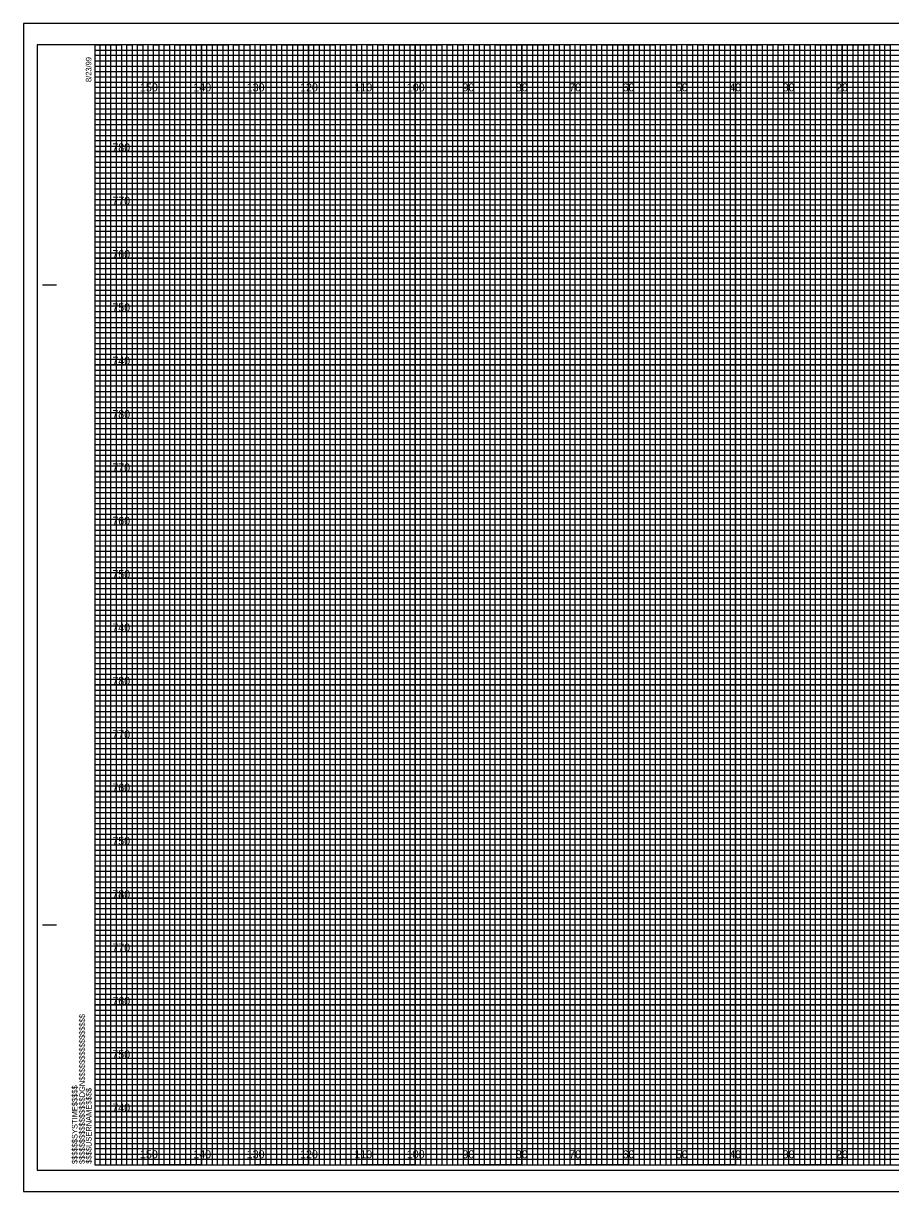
# Model space of a CAD drawing. Extents: x -13 to 323, y 215 to 434.
# Drawn here: x -13.4 to 149.1, y 215 to 434 of the extents above; entities that cross this region are included whole.
import ezdxf

# ---------------------------------------------------------------- set-up
doc = ezdxf.new("R2010")
doc.units = 0
for name, color, linetype in [('Prop XS Elevation Labels', 7, 'Continuous'), ('Prop XS Offset Labels', 7, 'Continuous'), ('Sheet Cross Section CELL', 7, 'Continuous'), ('Sheet Cross Section Grid Major CELL', 7, 'Continuous'), ('Sheet Cross Section Grid Middle CELL', 7, 'Continuous'), ('Sheet Cross Section Grid Minor 1 CELL', 7, 'Continuous'), ('Sheet Cross Section Grid Minor 2 CELL', 7, 'Continuous'), ('Sheet Cutting Line CELL', 7, 'Continuous'), ('Sheet DOT Grid CELL', 7, 'Continuous'), ('Sheet Plot Border Inside CELL', 7, 'Continuous'), ('Sheet Plot Border Outside CELL', 7, 'Continuous')]:
    doc.layers.add(name, color=color, linetype=linetype)

msp = doc.modelspace()

# ---------------------------------------------------------------- linework, layer by layer
at = {"layer": 'Sheet Cross Section CELL'}
for p, q in [((-9.8, 385), (-7.3, 385)), ((-9.7, 385), (-7.2, 385)), ((-9.8, 265), (-7.3, 265)), ((-9.7, 265), (-7.2, 265)), ((0, 220), (0, 220)), ((0, 220), (0, 220)), ((0, 220), (0, 220)), ((0, 220), (0, 220)), ((0, 220), (0, 220)), ((0, 220), (0, 220)), ((0, 220), (0, 220))]:
    msp.add_line(p, q, dxfattribs=at)
msp.add_lwpolyline([(320, 430), (0, 430), (0, 220), (320, 220)], close=True, dxfattribs=at)
at = {"layer": 'Sheet Cross Section Grid Major CELL'}
for p, q in [((10, 430), (0, 430)), ((10, 220), (10, 430)), ((30, 430), (20, 430)), ((20, 430), (20, 220)), ((30, 220), (30, 430)), ((50, 430), (40, 430)), ((40, 430), (40, 220)), ((50, 220), (50, 430)), ((70, 430), (60, 430)), ((60, 430), (60, 220)), ((70, 220), (70, 430)), ((90, 430), (80, 430)), ((80, 430), (80, 220)), ((90, 220), (90, 430)), ((110, 430), (100, 430)), ((100, 430), (100, 220)), ((110, 220), (110, 430)), ((130, 430), (120, 430)), ((120, 430), (120, 220)), ((130, 220), (130, 430)), ((150, 430), (140, 430)), ((140, 430), (140, 220)), ((20, 220), (10, 220)), ((40, 220), (30, 220)), ((60, 220), (50, 220)), ((80, 220), (70, 220)), ((100, 220), (90, 220)), ((120, 220), (110, 220)), ((140, 220), (130, 220))]:
    msp.add_line(p, q, dxfattribs=at)
for points in [[(0, 420), (320, 420), (320, 410), (0, 410)], [(0, 400), (320, 400), (320, 390), (0, 390)], [(0, 380), (320, 380), (320, 370), (0, 370)], [(0, 360), (320, 360), (320, 350), (0, 350)], [(0, 340), (320, 340), (320, 330), (0, 330)], [(0, 320), (320, 320), (320, 310), (0, 310)], [(0, 300), (320, 300), (320, 290), (0, 290)], [(0, 280), (320, 280), (320, 270), (0, 270)], [(0, 260), (320, 260), (320, 250), (0, 250)], [(0, 240), (320, 240), (320, 230), (0, 230)]]:
    msp.add_lwpolyline(points, dxfattribs=at)
at = {"layer": 'Sheet Cross Section Grid Middle CELL'}
for points in [[(0, 430), (5, 430), (5, 220), (15, 220), (15, 430), (25, 430), (25, 220), (35, 220), (35, 430), (45, 430), (45, 220), (55, 220), (55, 430), (65, 430), (65, 220), (75, 220), (75, 430), (85, 430), (85, 220), (95, 220), (95, 430), (105, 430), (105, 220), (115, 220), (115, 430), (125, 430), (125, 220), (135, 220), (135, 430), (145, 430), (145, 220), (155, 220)], [(0, 425), (275, 425)], [(0, 405), (320, 405), (320, 415), (0, 415)], [(0, 385), (320, 385), (320, 395), (0, 395)], [(0, 365), (320, 365), (320, 375), (0, 375)], [(0, 345), (320, 345), (320, 355), (0, 355)], [(0, 325), (320, 325), (320, 335), (0, 335)], [(0, 305), (320, 305), (320, 315), (0, 315)], [(0, 285), (320, 285), (320, 295), (0, 295)], [(0, 265), (320, 265), (320, 275), (0, 275)], [(0, 245), (320, 245), (320, 255), (0, 255)], [(0, 225), (320, 225), (320, 235), (0, 235)]]:
    msp.add_lwpolyline(points, dxfattribs=at)
at = {"layer": 'Sheet Cross Section Grid Minor 1 CELL'}
for p, q in [((0, 429), (260, 429)), ((260, 427.98), (0, 427.98)), ((0, 427.98), (0, 427)), ((0, 427), (260, 427)), ((260, 425.89), (0, 425.89)), ((0, 425.89), (0, 424)), ((0, 424), (320, 424))]:
    msp.add_line(p, q, dxfattribs=at)
for points in [[(0, 423), (270, 423), (320, 423), (320, 422), (0, 422)], [(0, 421), (320, 421), (320, 419), (0, 419)], [(0, 418), (320, 418), (320, 417), (0, 416.98)], [(0, 416), (320, 416), (320, 414), (0, 414)], [(0, 413), (320, 413), (320, 412), (0, 412)], [(0, 411), (320, 411), (320, 409), (0, 409)], [(0, 408), (320, 408), (320, 407), (0, 407)], [(0, 406), (320, 406), (320, 404), (0, 404)], [(0, 403), (320, 403), (320, 402), (0, 402)], [(0, 401), (320, 401), (320, 399), (0, 399)], [(0, 398), (320, 398), (320, 397), (0, 397)], [(0, 396), (320, 396), (320, 393.95), (320, 393), (320, 392), (0, 392)], [(0, 394), (320, 394), (320, 393), (0, 393)], [(0, 391), (320, 391), (320, 389), (0, 389.03)], [(0, 389.03), (320, 389), (320, 388), (0, 388)], [(0, 387), (320, 387), (320, 386), (0, 386)], [(0, 384), (320, 384), (320, 383), (0, 383)], [(0, 382), (320, 382), (320, 381), (0, 381)], [(-0.07, 378.89), (320, 378.89), (320, 377.88), (-0.07, 377.88)], [(0, 377), (320, 377), (320, 376), (0, 376)], [(0, 374), (320, 374), (320, 373), (0, 373)], [(0, 372), (320, 372), (320, 371), (0, 371)], [(0, 369), (320, 369), (320, 368), (0, 368)], [(0, 367), (320, 367), (320, 366), (0, 366)], [(0, 364), (320, 364), (320, 363), (0, 363)], [(0, 362), (320, 362), (320, 361), (0, 361)], [(0, 359), (320, 359), (319.99, 357.98), (0, 358)], [(0, 357), (320, 357), (320, 356), (0, 356)], [(0, 354), (320, 354), (320, 353), (0, 353)], [(0, 352), (320, 352), (320, 351), (0, 351)], [(0, 349), (320, 349), (320, 348), (0, 348)], [(0, 347), (320, 347), (320, 346), (0, 346)], [(0, 344), (320, 344), (320, 343), (0, 343)], [(0, 342), (320, 342), (320, 341), (0, 341)], [(0, 339), (320, 339), (320, 338), (0, 338)], [(0, 336.99), (320.07, 336.91), (320, 336), (0, 336)], [(0, 334), (320, 334), (320, 333), (0, 333)], [(0, 332), (320, 332), (320, 331), (0, 331)], [(0, 329), (320, 329), (320, 328), (0, 328)], [(0, 327), (320, 327), (320, 326), (0, 326)], [(0, 324), (320, 324), (320, 323), (0, 323)], [(0, 322), (320, 322), (320, 321), (0, 321)], [(0, 319), (320, 319), (320, 318), (0, 318)], [(0, 317), (320, 317), (320, 316), (0, 316)], [(0, 314), (320, 314), (320, 313), (0, 313)], [(0, 312), (320, 312), (320, 311), (0, 311)], [(0, 309), (320, 309), (320, 308), (0, 308)], [(0, 307), (320, 307), (320, 306), (0, 306)], [(0, 304), (320, 304), (320, 303), (0, 303)], [(0, 302), (320, 302), (320, 301), (0, 301)], [(0, 299), (320, 299), (319.99, 297.98), (0, 298)], [(0, 297), (320, 297), (320, 296), (0, 296)], [(0, 294), (320, 294), (320, 293), (0, 293)], [(0, 292), (320, 292), (320, 291), (0, 291)], [(0, 289), (320, 289), (320, 288), (0, 288)], [(0, 287), (320, 287), (320, 286), (0, 286)], [(0, 284), (320, 284), (320, 283), (0, 283)], [(0, 282), (320, 282), (320, 281), (0, 281)], [(0, 279), (320, 279), (320, 278), (0, 278)], [(0, 276.99), (320.07, 276.91), (320, 276), (0, 276)], [(0, 274), (320, 274), (320, 273), (0, 273)], [(0, 272), (320, 272), (320, 271), (0, 271)], [(0, 269), (320, 269), (320, 268), (0, 268)], [(0, 267), (320, 267), (320, 266), (0, 266)], [(0, 264), (320, 264), (320, 263), (0, 263)], [(0, 262), (320, 262), (320, 261), (0, 261)], [(0, 259), (320, 259), (320, 258), (0, 258)], [(0, 257), (320, 257), (320, 256), (0, 256)], [(0, 254), (320, 254), (320, 253), (0, 253)], [(0, 252), (320, 252), (320, 251), (0, 251)], [(0, 249), (320, 249), (320, 248), (0, 248)], [(0, 247), (320, 247), (320, 246), (0, 246)], [(0, 244), (320, 244), (320, 243), (0, 243)], [(0, 242), (320, 242), (320, 241), (0, 241)], [(0, 239), (320, 239), (320, 238), (0, 238)], [(0, 237), (320, 237), (320, 236), (0, 236)], [(0, 234), (320, 234), (320, 233), (0, 233)], [(0, 232), (320, 232), (320, 231), (0, 231)], [(0, 229), (320, 229), (320, 228), (0, 228)], [(0, 227), (320, 227), (320, 226), (0, 226)], [(0, 224), (320, 224), (320, 223), (0, 223)], [(0, 222), (320, 222), (320, 221), (0, 221)]]:
    msp.add_lwpolyline(points, dxfattribs=at)
at = {"layer": 'Sheet Cross Section Grid Minor 2 CELL'}
for points in [[(0, 220), (1, 220), (1, 430), (2, 430), (2, 220)], [(2, 220), (3, 220), (3, 430), (4, 430), (4, 220)], [(5, 220), (6, 220), (6, 430), (7, 430), (7, 220)], [(7, 220), (8, 220), (8, 430), (9, 430), (9, 220)], [(10, 220), (11, 220), (11, 430), (12, 430), (12, 220)], [(12, 220), (13, 220), (13, 430), (14, 430), (14, 220)], [(15, 220), (16, 220), (16, 430), (17, 430), (17, 220)], [(17, 220), (18, 220), (18, 430), (19, 430), (19, 220)], [(20, 220), (21, 220), (21, 430), (22, 430), (22, 220)], [(22, 220), (23, 220), (23, 430), (24, 430), (24, 220)], [(25, 220), (26, 220), (26, 430), (27, 430), (27, 220)], [(27, 220), (28, 220), (28, 430), (29, 430), (29, 220)], [(30, 220), (31, 220), (31, 430), (32, 430), (32, 220)], [(32, 220), (33, 220), (33, 430), (34, 430), (34, 220)], [(35, 220), (36, 220), (36, 430), (37, 430), (37, 220)], [(37, 220), (38, 220), (38, 430), (39, 430), (39, 220)], [(40, 220), (41, 220), (41, 430), (42, 430), (42, 220)], [(42, 220), (43, 220), (43, 430), (44, 430), (44, 220)], [(45, 220), (46, 220), (46, 430), (47, 430), (47, 220)], [(47, 220), (48, 220), (48, 430), (49, 430), (49, 220)], [(50, 220), (51, 220), (51, 430), (52, 430), (52, 220)], [(52, 220), (53, 220), (53, 430), (54, 430), (54, 220)], [(55, 220), (56, 220), (56, 430), (57, 430), (57, 220)], [(57, 220), (58, 220), (58, 430), (59, 430), (59, 220)], [(60, 220), (61, 220), (61, 430), (62, 430), (62, 220)], [(62, 220), (63, 220), (63, 430), (64, 430), (64, 220)], [(65, 220), (66, 220), (66, 430), (67, 430), (67, 220)], [(67, 220), (68, 220), (68, 430), (69, 430), (69, 220)], [(70, 220), (71, 220), (71, 430), (72, 430), (72, 220)], [(72, 220), (73, 220), (73, 430), (74, 430), (74, 220)], [(75, 220), (76, 220), (76, 430), (77, 430), (77, 220)], [(77, 220), (78, 220), (78, 430), (79, 430), (79, 220)], [(80, 220), (81, 220), (81, 430), (82, 430), (82, 220)], [(82, 220), (83, 220), (83, 430), (84, 430), (84, 220)], [(85, 220), (86, 220), (86, 430), (87, 430), (87, 220)], [(87, 220), (88, 220), (88, 430), (89, 430), (89, 220)], [(90, 220), (91, 220), (91, 430), (92, 430), (92, 220)], [(92, 220), (93, 220), (93, 430), (94, 430), (94, 220)], [(95, 220), (96, 220), (96, 430), (97, 430), (97, 220)], [(97, 220), (98, 220), (98, 430), (99, 430), (99, 220)], [(100, 220), (101, 220), (101, 430), (102, 430), (102, 220)], [(102, 220), (103, 220), (103, 430), (104, 430), (104, 220)], [(105, 220), (106, 220), (106, 430), (107, 430), (107, 220)], [(107, 220), (108, 220), (108, 430), (109, 430), (109, 220)], [(110, 220), (111, 220), (111, 430), (112, 430), (112, 220)], [(112, 220), (113, 220), (113, 430), (114, 430), (114, 220)], [(115, 220), (116, 220), (116, 430), (117, 430), (117, 220)], [(117, 220), (118, 220), (118, 430), (119, 430), (119, 220)], [(120, 220), (121, 220), (121, 430), (122, 430), (122, 220)], [(122, 220), (123, 220), (123, 430), (124, 430), (124, 220)], [(125, 220), (126, 220), (126, 430), (127, 430), (127, 220)], [(127, 220), (128, 220), (128, 430), (129, 430), (129, 220)], [(130, 220), (131, 220), (131, 430), (132, 430), (132, 220)], [(132, 220), (133, 220), (133, 430), (134, 430), (134, 220)], [(135, 220), (136, 220), (136, 430), (137, 430), (137, 220)], [(137, 220), (138, 220), (138, 430), (139, 430), (139, 220)], [(140, 220), (141, 220), (141, 430), (142, 430), (142, 220)], [(142, 220), (143, 220), (143, 430), (144, 430), (144, 220)], [(145, 220), (146, 220), (146, 430), (147, 430), (147, 220)], [(147, 220), (148, 220), (148, 430), (149, 430), (149, 220)]]:
    msp.add_lwpolyline(points, dxfattribs=at)
at = {"layer": 'Sheet Cutting Line CELL'}
for p, q in [((323.3, 434), (-13.4, 434)), ((-13.4, 434), (-13.4, 215)), ((-13.4, 215), (323.3, 215))]:
    msp.add_line(p, q, dxfattribs=at)
at = {"layer": 'Sheet DOT Grid CELL'}
for p, q in [((10, 220), (10, 430)), ((20, 220), (20, 430)), ((30, 220), (30, 430)), ((40, 220), (40, 430)), ((50, 220), (50, 430)), ((60, 220), (60, 430)), ((70, 220), (70, 430)), ((80, 220), (80, 430)), ((90, 220), (90, 430)), ((100, 220), (100, 430)), ((110, 220), (110, 430)), ((120, 220), (120, 430)), ((130, 220), (130, 430)), ((140, 220), (140, 430)), ((0, 420), (320, 420)), ((0, 410), (320, 410)), ((0, 400), (320, 400)), ((0, 390), (320, 390)), ((0, 380), (320, 380)), ((0, 370), (320, 370)), ((0, 360), (320, 360)), ((0, 350), (320, 350)), ((0, 340), (320, 340)), ((0, 330), (320, 330)), ((0, 320), (320, 320)), ((0, 310), (320, 310)), ((0, 300), (320, 300)), ((0, 290), (320, 290)), ((0, 280), (320, 280)), ((0, 270), (320, 270)), ((0, 260), (320, 260)), ((0, 250), (320, 250)), ((0, 240), (320, 240)), ((0, 230), (320, 230))]:
    msp.add_line(p, q, dxfattribs=at)
at = {"layer": 'Sheet Plot Border Inside CELL'}
msp.add_lwpolyline([(-10.8, 219), (322.4, 219), (322.4, 430), (-10.8, 430)], close=True, dxfattribs=at)
at = {"layer": 'Sheet Plot Border Outside CELL'}
msp.add_lwpolyline([(-13.4, 215), (323.3, 215), (323.3, 434), (-13.4, 434)], close=True, dxfattribs=at)

# ---------------------------------------------------------------- texts
at = {"layer": 'Prop XS Elevation Labels'}
for s, p in [('780', (3.26, 410)), ('770', (3.26, 400)), ('760', (3.26, 390)), ('750', (3.26, 380)), ('740', (3.26, 370)), ('780', (3.26, 360)), ('770', (3.26, 350)), ('760', (3.26, 340)), ('750', (3.26, 330)), ('740', (3.26, 320)), ('780', (3.26, 310)), ('770', (3.26, 300)), ('760', (3.26, 290)), ('750', (3.26, 280)), ('780', (3.26, 270)), ('740', (3.26, 270)), ('770', (3.26, 260)), ('760', (3.26, 250)), ('750', (3.26, 240)), ('740', (3.26, 230))]:
    msp.add_text(s, height=1.5, dxfattribs=at).set_placement(p)
at = {"layer": 'Prop XS Offset Labels'}
for s, p in [('150', (8.44, 421.25)), ('140', (18.44, 421.25)), ('130', (28.44, 421.25)), ('120', (38.44, 421.25)), ('110', (48.62, 421.25)), ('100', (58.44, 421.25)), ('90', (68.86, 421.25)), ('80', (78.86, 421.25)), ('70', (88.86, 421.25)), ('60', (98.86, 421.25)), ('50', (108.86, 421.25)), ('40', (118.86, 421.25)), ('30', (128.86, 421.25)), ('20', (138.86, 421.25)), ('150', (8.44, 221.25)), ('140', (18.44, 221.25)), ('130', (28.44, 221.25)), ('120', (38.44, 221.25)), ('110', (48.62, 221.25)), ('100', (58.44, 221.25)), ('90', (68.86, 221.25)), ('80', (78.86, 221.25)), ('70', (88.86, 221.25)), ('60', (98.86, 221.25)), ('50', (108.86, 221.25)), ('40', (118.86, 221.25)), ('30', (128.86, 221.25)), ('20', (138.86, 221.25))]:
    msp.add_text(s, height=1.5, dxfattribs=at).set_placement(p)
at = {"layer": 'Sheet Cross Section CELL'}
for s, p in [('8/23/99', (-0.65, 423)), ('$$$$$$$$$$$$$$$$DGN$$$$$$$$$$$$$$$$', (-1.88, 220.18)), ('$$$$$$SYSTIME$$$$$', (-3.26, 220.18)), ('$$$$USERNAME$$$$', (-0.62, 220.23))]:
    msp.add_text(s, height=1.05, rotation=90, dxfattribs=at).set_placement(p)

doc.saveas('drawing.dxf')
